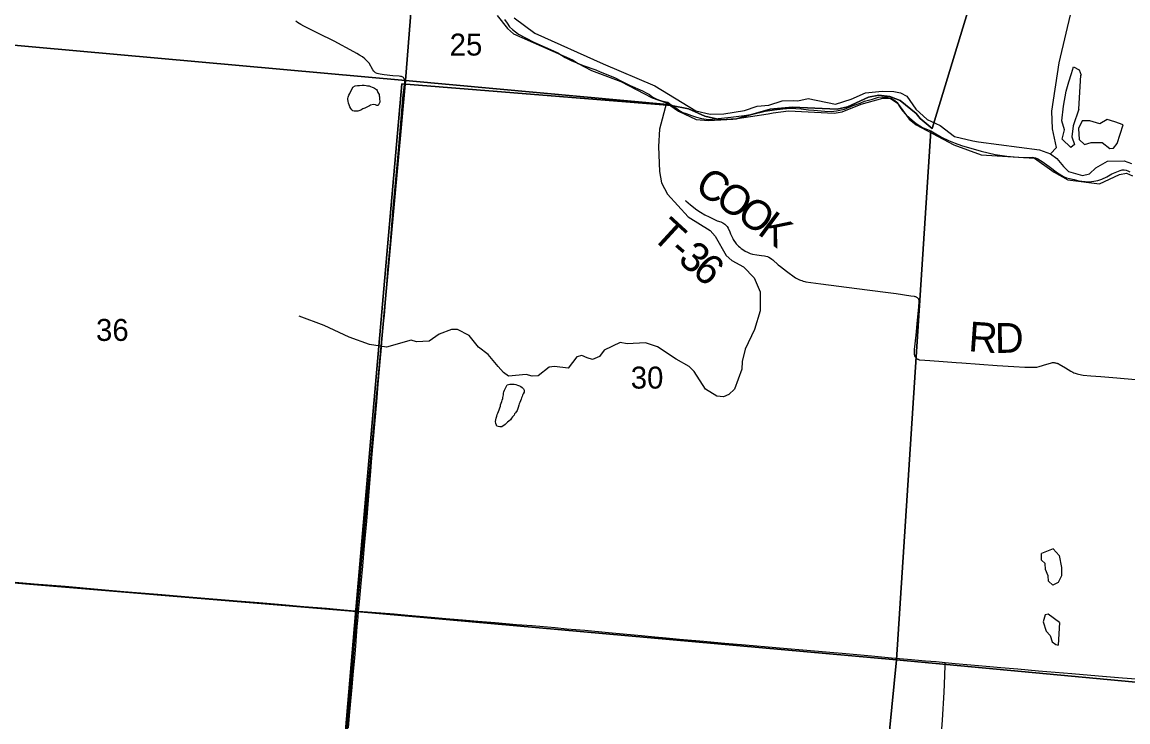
# Model space of a CAD drawing. Extents: x 1410790 to 1770854, y 448063 to 770588.
# Drawn here: x 1527172 to 1538300, y 586651 to 593697 of the extents above; entities that cross this region are included whole.
import ezdxf

# ---------------------------------------------------------------- set-up
doc = ezdxf.new("R2010")
doc.units = 0
for name, color, linetype in [('GM_X_County_Road', 7, 'Continuous'), ('GM_X_Major_River', 7, 'Continuous'), ('GM_X_Minor_Lake', 7, 'Continuous'), ('GM_X_Minor_River', 7, 'Continuous'), ('GM_X_Section', 7, 'Continuous'), ('GM_X_Section_Text', 7, 'Continuous'), ('GM_X_Township', 7, 'Continuous'), ('GM_X_Township_Road', 7, 'Continuous'), ('GM_X_Township_Road_Text', 7, 'Continuous')]:
    doc.layers.add(name, color=color, linetype=linetype)

msp = doc.modelspace()

# ---------------------------------------------------------------- linework, layer by layer
at = {"layer": 'GM_X_County_Road'}
for points in [[(1531015, 593133), (1531015, 593133), (1531014, 593133), (1531010, 593138), (1531004, 593142), (1530998, 593145), (1530989, 593148), (1530979, 593150), (1530966, 593151), (1530903, 593156), (1530816, 593165), (1530795, 593168), (1530775, 593171), (1530759, 593175), (1530744, 593180), (1530729, 593187), (1530719, 593195), (1530711, 593203), (1530703, 593215), (1530664, 593282), (1530654, 593295), (1530643, 593308), (1530621, 593328), (1530597, 593346), (1530568, 593364), (1530540, 593381), (1530512, 593396), (1530312, 593505), (1530156, 593583), (1530009, 593656), (1529978, 593672), (1529961, 593682), (1529945, 593692), (1529928, 593705)], [(1530558, 587767), (1530558, 587767), (1530566, 587861), (1530584, 588044), (1530601, 588220), (1530619, 588426), (1530641, 588671), (1530668, 589011), (1530682, 589175), (1530693, 589309), (1530741, 589874), (1530755, 590051), (1530771, 590240), (1530788, 590421), (1530797, 590521), (1530804, 590603), (1530813, 590688), (1530818, 590743), (1530835, 590962), (1530854, 591198), (1530880, 591482), (1530904, 591786), (1530928, 592037), (1530965, 592441), (1530974, 592564), (1530984, 592685), (1530997, 592847), (1531007, 592966), (1531023, 593091), (1531023, 593098), (1531022, 593107), (1531022, 593114), (1531020, 593120), (1531018, 593127), (1531015, 593133)], [(1526795, 588084), (1527295, 588042), (1527605, 588016), (1527971, 587984), (1528197, 587965), (1528537, 587936), (1528851, 587910), (1529335, 587871), (1529554, 587852), (1529753, 587837), (1530008, 587814), (1530234, 587795), (1530374, 587783), (1530558, 587767)], [(1530456, 586590), (1530470, 586753), (1530494, 587002), (1530505, 587126), (1530520, 587296), (1530530, 587413), (1530539, 587518), (1530545, 587609), (1530548, 587642), (1530553, 587704), (1530558, 587767)], [(1530558, 587767), (1530917, 587738), (1531054, 587726), (1531289, 587704), (1531438, 587692), (1531603, 587678), (1531757, 587665), (1531933, 587651), (1532146, 587633), (1532306, 587620), (1532538, 587601), (1532655, 587589), (1532835, 587573), (1533074, 587550), (1533407, 587521), (1533541, 587507), (1533655, 587496), (1533789, 587485), (1534034, 587463), (1534243, 587445), (1534452, 587426), (1534756, 587401), (1534870, 587391), (1535187, 587363), (1535302, 587353), (1535426, 587342), (1535573, 587329), (1535720, 587316), (1535922, 587297), (1536121, 587279), (1536265, 587267), (1536370, 587258), (1536462, 587249)], [(1536462, 587249), (1536562, 587240), (1536719, 587226), (1536873, 587213), (1537021, 587199), (1537194, 587184), (1537399, 587166), (1537569, 587151), (1537737, 587137), (1537927, 587122), (1538043, 587111), (1538246, 587093), (1538383, 587083)]]:
    msp.add_lwpolyline(points, dxfattribs=at)
at = {"layer": 'GM_X_Major_River'}
for points in [[(1531952, 593764), (1532056, 593633), (1532118, 593578), (1532712, 593317), (1532769, 593279), (1532903, 593208), (1533197, 593100), (1533512, 592934), (1533657, 592883), (1533777, 592799), (1533957, 592715), (1534079, 592705), (1534326, 592719), (1534679, 592772), (1534731, 592785), (1534886, 592804), (1535343, 592781), (1535424, 592793), (1535617, 592871), (1535835, 592930), (1535907, 592930), (1535982, 592881), (1536099, 592721), (1536168, 592663), (1536550, 592462), (1536824, 592361), (1537359, 592326), (1537557, 592187), (1537697, 592110), (1538014, 592068), (1538216, 592162), (1538285, 592176), (1538348, 592148)], [(1532124, 593741), (1532331, 593584), (1533020, 593277), (1533538, 593054), (1533953, 592805), (1534097, 592771), (1534233, 592772), (1534441, 592808), (1534569, 592850), (1534687, 592860), (1534821, 592904), (1534930, 592907), (1534980, 592905), (1535083, 592926), (1535356, 592871), (1535516, 592920), (1535660, 592986), (1535827, 593001), (1535944, 592999), (1536011, 592985), (1536075, 592951), (1536167, 592819), (1536280, 592715), (1536410, 592655), (1536555, 592546), (1536738, 592500), (1536798, 592490), (1537412, 592412), (1537521, 592371), (1537585, 592323), (1537651, 592244), (1537703, 592192), (1537843, 592154), (1537913, 592170), (1537977, 592228), (1538096, 592296), (1538261, 592301), (1538338, 592273)]]:
    msp.add_lwpolyline(points, dxfattribs=at)
at = {"layer": 'GM_X_Minor_Lake'}
for points in [[(1537806, 592819), (1537750, 592653), (1537736, 592543), (1537763, 592464), (1537726, 592433), (1537638, 592519), (1537661, 592611), (1537635, 592704), (1537652, 592852), (1537679, 593002), (1537705, 593096), (1537731, 593179), (1537752, 593247), (1537810, 593216), (1537829, 593163)], [(1537806, 592819), (1537828, 593164)], [(1530500, 593042), (1530525, 593056), (1530549, 593060), (1530569, 593059), (1530593, 593061), (1530615, 593061), (1530633, 593058), (1530649, 593056), (1530665, 593054), (1530677, 593050), (1530695, 593042), (1530705, 593037), (1530717, 593031), (1530727, 593025), (1530737, 593017), (1530745, 593007), (1530753, 592989), (1530759, 592979), (1530764, 592968), (1530766, 592954), (1530770, 592944), (1530770, 592928), (1530770, 592916), (1530772, 592904), (1530772, 592890), (1530765, 592876), (1530757, 592858), (1530743, 592858), (1530727, 592865), (1530709, 592867), (1530679, 592859), (1530669, 592853), (1530647, 592844), (1530635, 592836), (1530620, 592830), (1530602, 592822), (1530590, 592816), (1530580, 592810), (1530570, 592806), (1530560, 592802), (1530550, 592799), (1530540, 592799), (1530530, 592799), (1530514, 592801), (1530500, 592805), (1530490, 592813), (1530480, 592826), (1530470, 592844), (1530464, 592864), (1530458, 592882), (1530455, 592902), (1530451, 592916), (1530451, 592928), (1530453, 592942), (1530457, 592952), (1530461, 592962), (1530470, 592978), (1530500, 593042)], [(1538251, 592661), (1538170, 592694), (1538092, 592716), (1538019, 592674), (1537916, 592704), (1537840, 592704), (1537804, 592626), (1537810, 592514), (1537865, 592466), (1537929, 592483), (1538040, 592485), (1538119, 592425), (1538155, 592428), (1538192, 592473)], [(1538192, 592473), (1538251, 592661)], [(1532052, 590044), (1532080, 590050), (1532102, 590051), (1532124, 590051), (1532140, 590049), (1532158, 590043), (1532178, 590034), (1532192, 590028), (1532206, 590018), (1532218, 590006), (1532226, 589992), (1532224, 589970), (1532215, 589954), (1532209, 589940), (1532203, 589928), (1532197, 589914), (1532193, 589900), (1532187, 589882), (1532180, 589866), (1532174, 589852), (1532170, 589840), (1532164, 589818), (1532153, 589786), (1532137, 589764), (1532129, 589752), (1532123, 589738), (1532108, 589722), (1532098, 589708), (1532086, 589694), (1532072, 589678), (1532058, 589669), (1532047, 589659), (1532035, 589647), (1532001, 589623), (1531979, 589623), (1531963, 589624), (1531951, 589628), (1531947, 589638), (1531939, 589656), (1531937, 589676), (1531940, 589694), (1531942, 589710), (1531948, 589730), (1531954, 589746), (1531960, 589760), (1531965, 589776), (1531973, 589794), (1531979, 589812), (1531985, 589830), (1531987, 589844), (1531994, 589860), (1532000, 589876), (1532002, 589892), (1532010, 589908), (1532010, 589918), (1532012, 589930), (1532017, 589944), (1532017, 589962), (1532021, 589974), (1532027, 589992), (1532052, 590044)], [(1537547, 588393), (1537608, 588325), (1537631, 588204), (1537632, 588120), (1537600, 588054), (1537544, 588028), (1537501, 588069), (1537498, 588121), (1537471, 588186), (1537466, 588246), (1537429, 588281), (1537430, 588347)], [(1537547, 588393), (1537430, 588347)], [(1537611, 587651), (1537498, 587736), (1537466, 587728), (1537446, 587659), (1537477, 587566), (1537518, 587521), (1537539, 587456), (1537576, 587429), (1537600, 587423)], [(1537611, 587651), (1537600, 587423)]]:
    msp.add_lwpolyline(points, dxfattribs=at)
at = {"layer": 'GM_X_Minor_River'}
for points in [[(1537521, 592371), (1537582, 592434), (1537543, 592622), (1537535, 592800), (1537607, 593286), (1537735, 593827), (1537782, 594181), (1537862, 594681), (1537795, 594933), (1537773, 595136), (1537770, 595197), (1537834, 595386), (1537845, 595505)], [(1533657, 592883), (1533588, 592618), (1533577, 592444), (1533586, 592191), (1533608, 592080), (1533668, 591964), (1533875, 591735), (1534097, 591600), (1534148, 591541), (1534259, 591346), (1534316, 591295), (1534433, 591234), (1534539, 591123), (1534598, 590980), (1534600, 590791), (1534543, 590602), (1534449, 590405), (1534418, 590279), (1534415, 590203), (1534341, 590002), (1534285, 589949), (1534229, 589924), (1534163, 589930), (1534050, 590002), (1533937, 590179), (1533884, 590231), (1533753, 590304), (1533565, 590426), (1533444, 590469), (1533261, 590459), (1533190, 590472), (1533030, 590393), (1532984, 590330), (1532912, 590300), (1532858, 590317), (1532806, 590340), (1532754, 590325), (1532668, 590211), (1532530, 590230), (1532477, 590221), (1532366, 590137), (1532305, 590132), (1532244, 590149), (1532067, 590133), (1532016, 590170), (1531963, 590230), (1531861, 590350), (1531764, 590425), (1531670, 590541), (1531553, 590602), (1531493, 590603), (1531370, 590555), (1531268, 590483), (1531140, 590478), (1531088, 590493), (1530840, 590424), (1530667, 590450), (1530462, 590523), (1530211, 590641), (1529961, 590736)]]:
    msp.add_lwpolyline(points, dxfattribs=at)
at = {"layer": 'GM_X_Section'}
for points in [[(1531426, 598513), (1531493, 598506), (1531320, 597039), (1531072, 595638), (1531092, 595622), (1531116, 595520), (1531165, 595359), (1531180, 595303), (1531189, 595260), (1531194, 595212), (1531196, 595192), (1531032, 593110), (1525634, 593594), (1526072, 598936)], [(1531032, 593110), (1530541, 587762), (1525157, 588213), (1525634, 593594)], [(1531032, 593110), (1533703, 592863), (1533752, 592833), (1533790, 592804), (1533820, 592787), (1533855, 592775), (1533907, 592756), (1533959, 592739), (1534010, 592726), (1534056, 592719), (1534094, 592717), (1534148, 592722), (1534305, 592739), (1534437, 592755), (1534525, 592769), (1534650, 592799), (1534744, 592815), (1534826, 592824), (1534906, 592829), (1535012, 592823), (1535086, 592815), (1535138, 592809), (1535249, 592801), (1535313, 592797), (1535369, 592805), (1535448, 592821), (1535534, 592856), (1535605, 592880), (1535649, 592900), (1535731, 592922), (1535792, 592941), (1535830, 592944), (1535874, 592940), (1535915, 592931), (1535951, 592912), (1535977, 592888), (1536002, 592848), (1536031, 592805), (1536061, 592769), (1536106, 592730), (1536171, 592675), (1536234, 592636), (1536318, 592602), (1535973, 587276), (1530541, 587762)], [(1525157, 588213), (1530541, 587762), (1530107, 582421), (1524728, 582874)], [(1530541, 587762), (1535973, 587276), (1535447, 581966), (1530107, 582421)]]:
    msp.add_lwpolyline(points, close=True, dxfattribs=at)
for points in [[(1532026, 593724), (1532052, 593686), (1532077, 593650), (1532107, 593621), (1532136, 593598), (1532168, 593576), (1532239, 593537), (1532322, 593495), (1532435, 593445), (1532491, 593420), (1532562, 593387), (1532638, 593342), (1532703, 593307), (1532755, 593286), (1532818, 593261), (1532945, 593215), (1532991, 593196), (1533082, 593160), (1533140, 593135), (1533199, 593106), (1533292, 593057), (1533415, 593004), (1533451, 592986), (1533485, 592967), (1533508, 592949), (1533532, 592934), (1533560, 592922), (1533596, 592907), (1533638, 592899), (1533671, 592892), (1533703, 592863), (1531032, 593110), (1531196, 595192)], [(1541253, 586782), (1535973, 587276), (1536318, 592602), (1536351, 592582), (1536424, 592540), (1536496, 592505), (1536561, 592478), (1536625, 592455), (1536824, 592399), (1536963, 592365), (1537081, 592347), (1537157, 592340), (1537249, 592332), (1537293, 592335), (1537337, 592336), (1537369, 592330), (1537394, 592319), (1537436, 592295), (1537507, 592244), (1537590, 592178), (1537653, 592141), (1537683, 592129), (1537711, 592122), (1537759, 592111), (1537808, 592100), (1537870, 592091), (1537910, 592089), (1537958, 592096), (1537998, 592103), (1538037, 592114), (1538089, 592139), (1538139, 592169), (1538222, 592203), (1538242, 592209), (1538264, 592210), (1538282, 592206), (1538298, 592200), (1538318, 592189)], [(1535447, 581966), (1535973, 587276), (1541253, 586782), (1540986, 583288)]]:
    msp.add_lwpolyline(points, dxfattribs=at)
at = {"layer": 'GM_X_Township'}
for points in [[(1530071, 582399), (1530526, 587739), (1530849, 591434), (1530993, 593074), (1533706, 592857), (1533879, 592823), (1534043, 592749), (1534205, 592712), (1534360, 592724), (1534699, 592821), (1534926, 592839), (1535376, 592820), (1535479, 592845), (1535691, 592941), (1535795, 592962), (1535904, 592947), (1536008, 592908), (1536169, 592776), (1536209, 592725), (1536332, 592626), (1536839, 594304), (1537814, 597533), (1538385, 599427)], [(1538385, 599427), (1537814, 597533), (1536839, 594304), (1536332, 592626), (1536209, 592725), (1536169, 592776), (1536008, 592908), (1535904, 592947), (1535795, 592962), (1535691, 592941), (1535479, 592845), (1535376, 592820), (1534926, 592839), (1534699, 592821), (1534360, 592724), (1534205, 592712), (1534043, 592749), (1533879, 592823), (1533706, 592857), (1530993, 593074), (1530849, 591434), (1530526, 587739), (1530071, 582399)]]:
    msp.add_lwpolyline(points, dxfattribs=at)
at = {"layer": 'GM_X_Township_Road'}
for points in [[(1533848, 591902), (1533851, 591898), (1533900, 591857), (1533929, 591833), (1533948, 591816), (1533972, 591799), (1534000, 591782), (1534042, 591758), (1534088, 591735), (1534148, 591706), (1534168, 591697), (1534205, 591685), (1534225, 591675), (1534244, 591663), (1534258, 591650), (1534269, 591638), (1534278, 591621), (1534294, 591586), (1534302, 591565), (1534311, 591545), (1534323, 591519), (1534328, 591508), (1534335, 591497), (1534350, 591476), (1534359, 591465), (1534369, 591454), (1534382, 591441), (1534395, 591430), (1534410, 591418), (1534425, 591407), (1534449, 591391), (1534472, 591379), (1534498, 591368), (1534524, 591362), (1534566, 591355), (1534614, 591348), (1534643, 591343), (1534657, 591340), (1534672, 591336), (1534687, 591330), (1534704, 591320), (1534716, 591311), (1534727, 591302), (1534782, 591254), (1534804, 591236), (1534864, 591190), (1534956, 591123), (1534969, 591115), (1534983, 591108), (1534995, 591103), (1535006, 591098), (1535018, 591094), (1535032, 591090), (1535048, 591086), (1535060, 591083), (1535210, 591063), (1535572, 591014), (1535860, 590977), (1535967, 590963), (1536116, 590942), (1536148, 590937), (1536156, 590935), (1536163, 590933), (1536169, 590930), (1536174, 590928), (1536179, 590924), (1536183, 590921), (1536186, 590918), (1536189, 590914), (1536192, 590910), (1536194, 590905), (1536195, 590901), (1536196, 590896), (1536197, 590892), (1536197, 590889), (1536197, 590885), (1536197, 590879), (1536193, 590830), (1536181, 590696), (1536165, 590546), (1536150, 590399), (1536149, 590370), (1536149, 590362), (1536149, 590354), (1536151, 590345), (1536153, 590338), (1536155, 590331), (1536159, 590326), (1536162, 590322), (1536165, 590318), (1536172, 590312), (1536177, 590308), (1536183, 590304), (1536189, 590302), (1536194, 590300), (1536200, 590298), (1536205, 590298), (1536308, 590290), (1536441, 590280), (1536571, 590271), (1536630, 590266), (1536984, 590240), (1537153, 590228), (1537262, 590223), (1537320, 590221), (1537357, 590221), (1537370, 590222), (1537383, 590224), (1537408, 590229), (1537483, 590253), (1537521, 590264), (1537530, 590266), (1537540, 590268), (1537548, 590268), (1537557, 590268), (1537565, 590267), (1537573, 590266), (1537580, 590264), (1537589, 590262), (1537593, 590260)], [(1537593, 590260), (1537599, 590258), (1537610, 590253), (1537672, 590217), (1537727, 590184), (1537746, 590173), (1537757, 590167), (1537769, 590162), (1537779, 590158), (1537791, 590154), (1537804, 590151), (1537820, 590148), (1537834, 590145), (1537849, 590143), (1537927, 590135), (1538028, 590127), (1538188, 590115), (1538378, 590100)], [(1536429, 586582), (1536434, 586670), (1536451, 586950), (1536454, 587029), (1536461, 587219), (1536462, 587249)]]:
    msp.add_lwpolyline(points, dxfattribs=at)

# ---------------------------------------------------------------- texts
at = {"layer": 'GM_X_Section_Text'}
for s, p in [('25', (1531475, 593360)), ('36', (1527916, 590487)), ('30', (1533297, 590007))]:
    msp.add_text(s, height=221, rotation=0, dxfattribs=at).set_placement(p)
at = {"layer": 'GM_X_Township_Road_Text'}
for s, rotation, p in [('C', 327.1641, (1533926, 592003)), ('O', 326.0755, (1534132, 591870)), ('O', 324.1706, (1534349, 591724)), ('K', 323.49, (1534562, 591570)), ('T', 317.4674, (1533495, 591530)), ('-', 319.0558, (1533667, 591372)), ('3', 319.1972, (1533761, 591291)), ('6', 319.7975, (1533903, 591168)), ('R', 355.8475, (1536689, 590384)), ('D', 1.0077, (1536964, 590365))]:
    msp.add_text(s, height=300, rotation=rotation, dxfattribs=at).set_placement(p)

doc.saveas('drawing.dxf')
